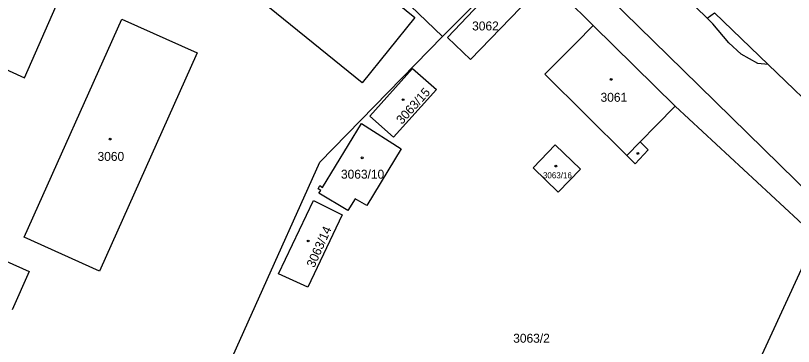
# Model space of a CAD drawing. Extents: x -527335 to -526256, y -1079142 to -1077836.
# Drawn here: x -526725 to -526577.1, y -1078894.6 to -1078831.7 of the extents above; entities that cross this region are included whole.
import ezdxf

# ---------------------------------------------------------------- set-up
doc = ezdxf.new("R2010")
doc.units = 0
for name, color, linetype in [('Hranice parcel', 7, 'Continuous'), ('Parcelní čísla', 7, 'Continuous'), ('Vnitřní kresba', 7, 'Continuous'), ('Značky budov', 7, 'Continuous')]:
    doc.layers.add(name, color=color, linetype=linetype)

msp = doc.modelspace()

# ---------------------------------------------------------------- linework, layer by layer
at = {"layer": 'Hranice parcel'}
for p, q in [((-526615.23, -1078833.62), (-526628.58, -1078820.26)), ((-526599.63, -1078848.92), (-526615.23, -1078833.62)), ((-526572.83, -1078873.83), (-526599.63, -1078848.92))]:
    msp.add_line(p, q, dxfattribs=at)
for points in [[(-526736.02, -1078622.71), (-526735.76, -1078656.09), (-526735.85, -1078660.53), (-526735.52, -1078663.69), (-526734.95, -1078666.12), (-526732.77, -1078674.37), (-526729.8, -1078686.09), (-526729.09, -1078688.53), (-526728.19, -1078690.47), (-526724.67, -1078698.8), (-526723.91, -1078700.57), (-526723.02, -1078702.2), (-526717.26, -1078711.17), (-526716.15, -1078712.7), (-526714.92, -1078714.22), (-526690.33, -1078738.18), (-526681.83, -1078746.32), (-526638.92, -1078788.12), (-526632.34, -1078794.49), (-526593.57, -1078832.2), (-526592.15, -1078831.2)], [(-526659.11, -1078844.46), (-526705.02, -1078807.32), (-526694.99, -1078794.92), (-526649.08, -1078832.06), (-526659.11, -1078844.46)], [(-526674.52, -1078803.28), (-526675.67, -1078805.16), (-526643.83, -1078835.71)], [(-526643.83, -1078835.71), (-526634.9, -1078826.67), (-526632.69, -1078824.43), (-526628.58, -1078820.26)], [(-526631.64, -1078823.97), (-526642.87, -1078835.86), (-526638.55, -1078840.04), (-526627.14, -1078828.22), (-526631.64, -1078823.97)], [(-526709.05, -1078880.27), (-526723.39, -1078873.86), (-526704.82, -1078832.36), (-526690.48, -1078838.76), (-526709.05, -1078880.27)], [(-526592.15, -1078831.2), (-526581.94, -1078841.02), (-526570.51, -1078852.02), (-526552.02, -1078869.8)], [(-526615.23, -1078833.62), (-526618.53, -1078836.95), (-526624.38, -1078842.86), (-526608.84, -1078858.29), (-526607.26, -1078859.86), (-526604.74, -1078857.22), (-526606.29, -1078855.69), (-526603.19, -1078852.55), (-526599.63, -1078848.92)], [(-526691.64, -1078914.07), (-526667.18, -1078859.55), (-526643.83, -1078835.71)], [(-526649.54, -1078841.76), (-526645, -1078845.77), (-526653.17, -1078854.83), (-526657.67, -1078850.82), (-526649.54, -1078841.76)], [(-526793.27, -1078848.55), (-526782.84, -1078853.23), (-526722.4, -1078880.36), (-526725.68, -1078887.67)], [(-526651.69, -1078857.04), (-526658.24, -1078867.78), (-526660.43, -1078866.54), (-526661.82, -1078868.79), (-526667.33, -1078865.47), (-526667, -1078864.94), (-526667.49, -1078864.63), (-526667.14, -1078864.04), (-526666.65, -1078864.37), (-526659.26, -1078852.22), (-526651.69, -1078857.04)], [(-526617.64, -1078860.92), (-526621.88, -1078865.27), (-526626.63, -1078860.62), (-526622.42, -1078856.27), (-526617.64, -1078860.92)], [(-526668.38, -1078866.89), (-526662.92, -1078869.6), (-526669.42, -1078883.36), (-526675.01, -1078880.82), (-526668.38, -1078866.89)], [(-526572.83, -1078873.83), (-526575.65, -1078879.95), (-526588.32, -1078907.48)]]:
    msp.add_lwpolyline(points, dxfattribs=at)
at = {"layer": 'Vnitřní kresba'}
for p, q in [((-526598.1, -1078842.1), (-526649.54, -1078791.39)), ((-526723.31, -1078843.53), (-526716.16, -1078827.32)), ((-526592.47, -1078833.26), (-526593.57, -1078832.2)), ((-526589.42, -1078836.86), (-526592.47, -1078833.26)), ((-526735.32, -1078838.08), (-526723.31, -1078843.53)), ((-526587.09, -1078839.03), (-526589.42, -1078836.86)), ((-526583.93, -1078840.82), (-526587.09, -1078839.03)), ((-526581.94, -1078841.02), (-526583.93, -1078840.82)), ((-526483.62, -1078954.28), (-526598.1, -1078842.1)), ((-526608.84, -1078858.29), (-526606.29, -1078855.69))]:
    msp.add_line(p, q, dxfattribs=at)
at = {"layer": 'Značky budov'}
for centre in [(-526611.79, -1078843.84), (-526651.35, -1078847.69), (-526707.05, -1078855.18), (-526659.13, -1078858.76), (-526606.7, -1078857.9), (-526622.3, -1078860.31), (-526669.39, -1078874.56)]:
    msp.add_circle(centre, 0.175, dxfattribs=at)

# ---------------------------------------------------------------- texts
at = {"layer": 'Parcelní čísla'}
for s, height, p in [('3062', 1.7, (-526638.22, -1078834.53)), ('3061', 1.7, (-526613.81, -1078848.09)), ('3060', 1.7, (-526709.42, -1078859.33)), ('3063/10', 1.7, (-526663.15, -1078862.71)), ('3063/16', 1.139, (-526624.76, -1078862.64)), ('3063/2', 1.7, (-526630.41, -1078893.9))]:
    msp.add_text(s, height=height, dxfattribs=at).set_placement(p)
for s, rotation, p in [('3063/15', 48, (-526651.56, -1078852.49)), ('3063/14', 66, (-526668.23, -1078879.76))]:
    msp.add_text(s, height=1.7, rotation=rotation, dxfattribs=at).set_placement(p)

doc.saveas('drawing.dxf')
